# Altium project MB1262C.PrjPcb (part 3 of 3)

## Sheet USB_Host_Hub&OTG.SchDoc: USB_Host_Hub
size A3; DocumentNumber: MB1262; Revision: C-01; SheetNumber: 8; SheetTotal: 17; Project: STM32MP15x-EVAL
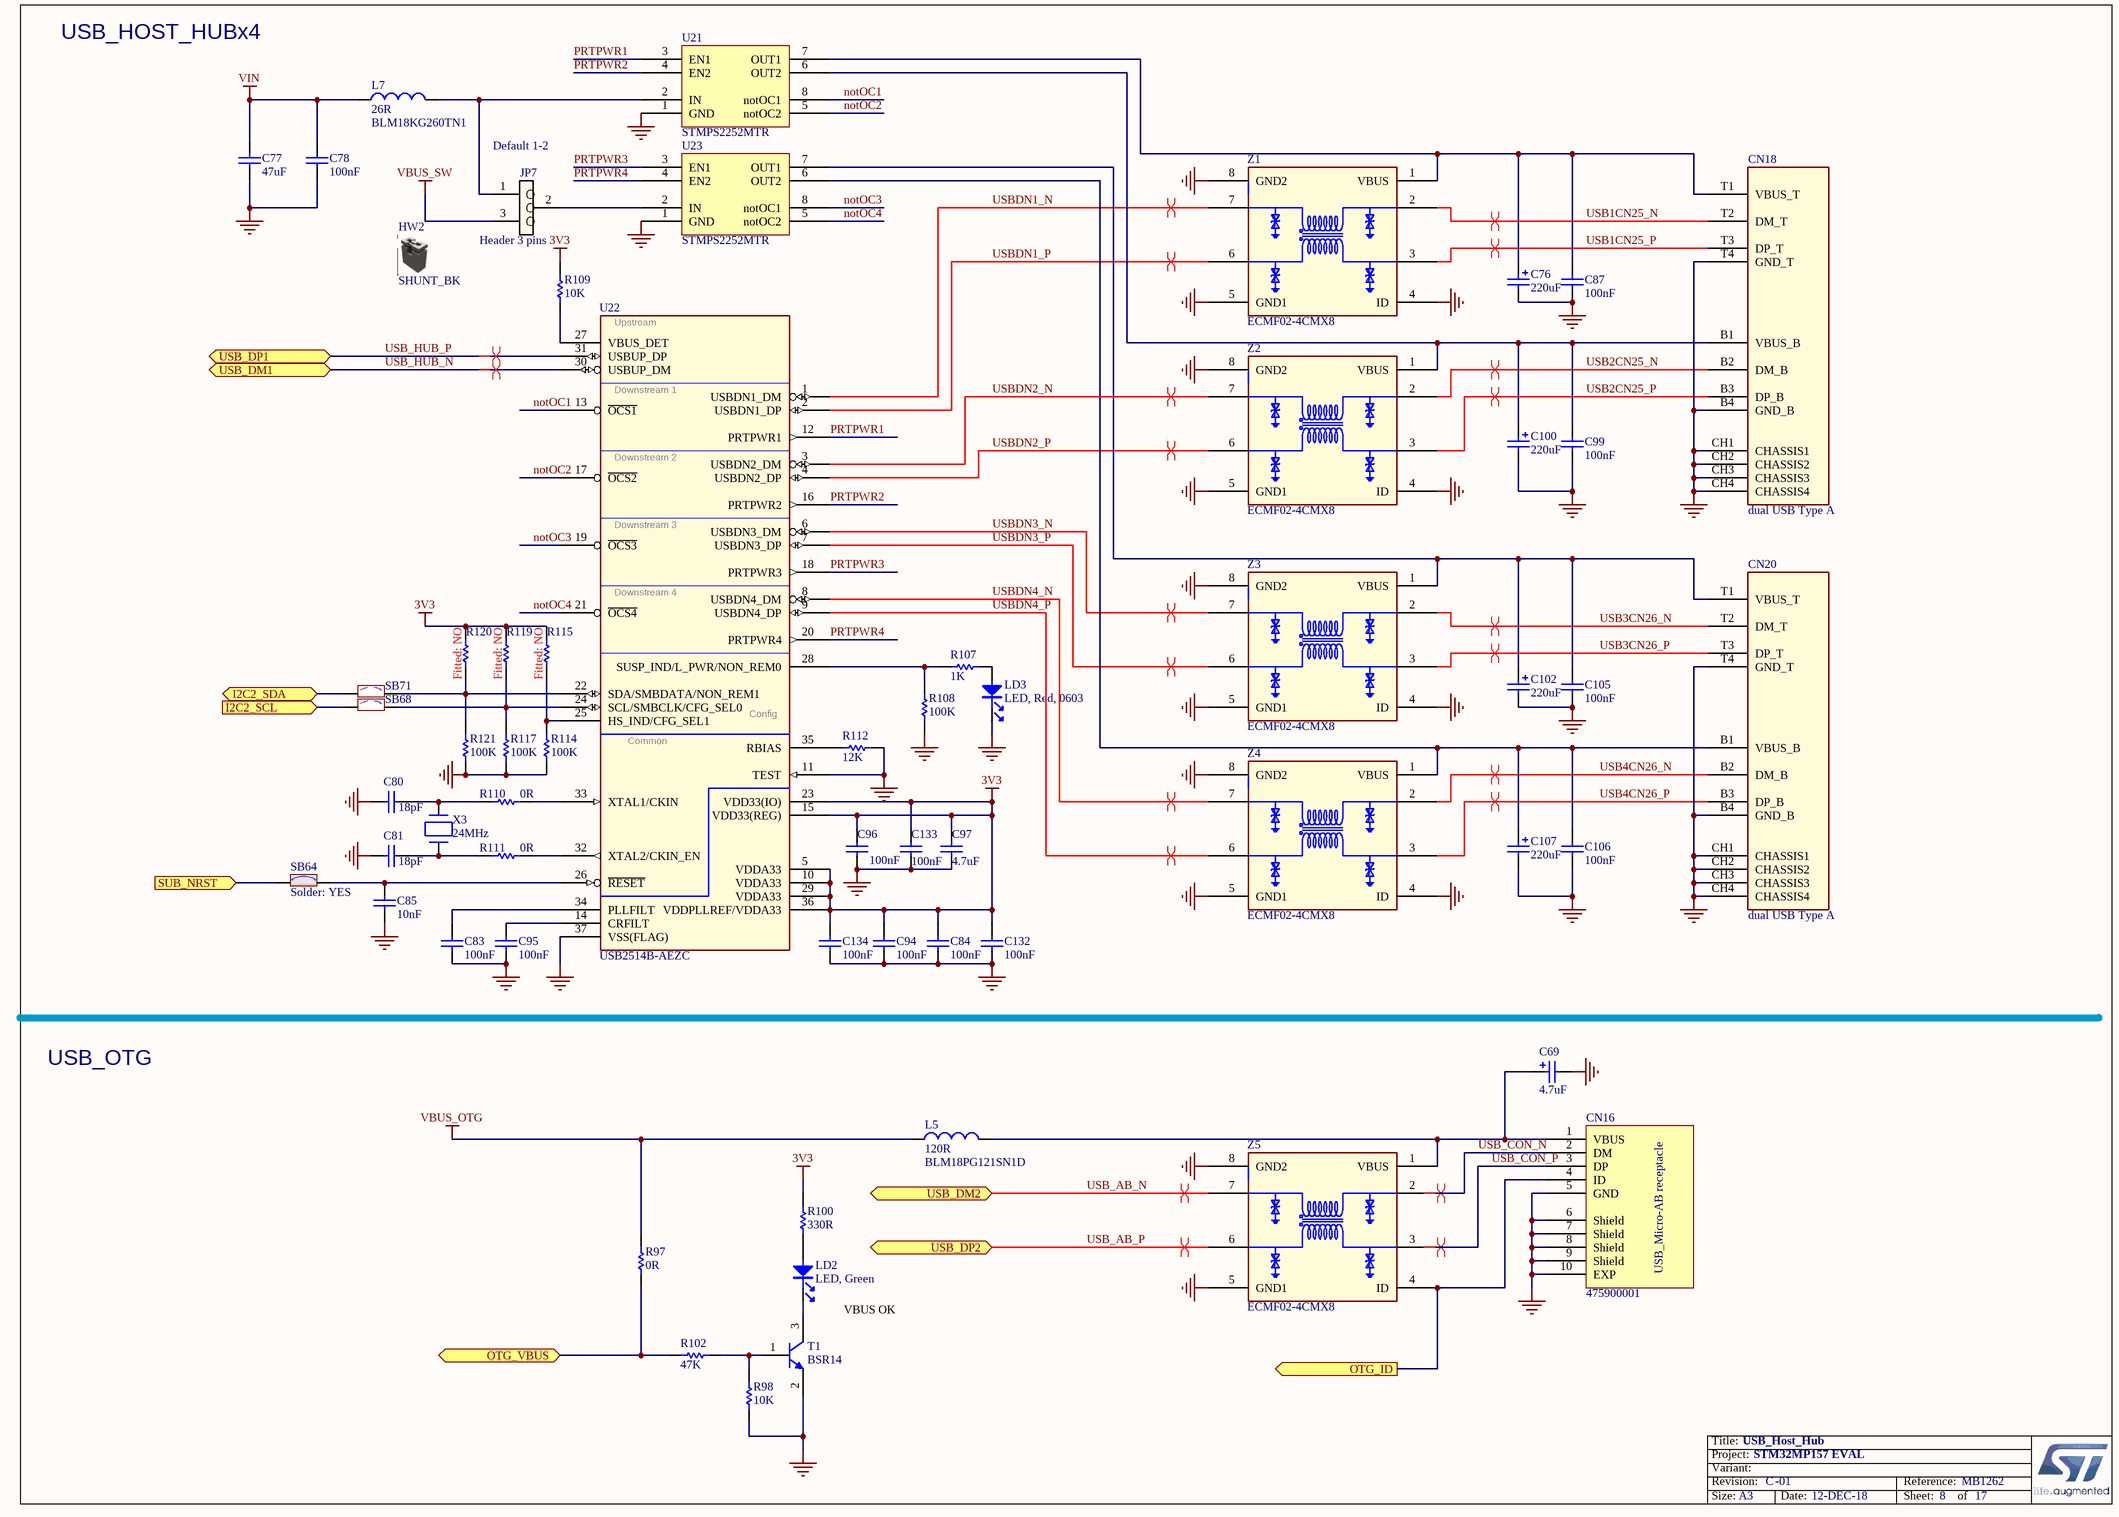
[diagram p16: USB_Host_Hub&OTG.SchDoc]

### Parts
C69  4.7uF  [CPOL_TAJ-A_1206_H180]
C76  220uF  [CPOL_TAJ-C_2312_H2P6]
C77  47uF  [C0805]
C78  100nF  [C0402]
C80  18pF  [C0402]
C81  18pF  [C0402]
C83  100nF  [C0402]
C84  100nF  [C0402]
C85  10nF  [C0402]
C87  100nF  [C0402]
C94  100nF  [C0402]
C95  100nF  [C0402]
C96  100nF  [C0402]
C97  4.7uF  [C0402]
C99  100nF  [C0402]
C100  220uF  [CPOL_TAJ-C_2312_H2P6]
C102  220uF  [CPOL_TAJ-C_2312_H2P6]
C105  100nF  [C0402]
C106  100nF  [C0402]
C107  220uF  [CPOL_TAJ-C_2312_H2P6]
C132  100nF  [C0402]
C133  100nF  [C0402]
C134  100nF  [C0402]
CN16  475900001  [CON_USBMICROAB_MOLEX_47590-0001_H3]
CN18  dual USB Type A  [CON_DUAL-USB-TYPE-A_CONEXCON_5600-3081]
CN20  dual USB Type A  [CON_DUAL-USB-TYPE-A_CONEXCON_5600-3081]
HW2  SHUNT_BK  (mechanical)
JP7  Header 3 pins  [CON_SAMTEC_TSW-103-07-F-S]
L5  120R  Manuf_Part_1: BLM18PG121SN1D  [FIL_0603_H065]
L7  26R  Manuf_Part_1: BLM18KG260TN1  [FIL_0603_H065]
LD2  LED, Green  [LED_0603_GREEN]
LD3  LED, Red, 0603  [LED_0603_RED]
R97  0R  [R0402]
R98  10K  [R0402]
R100  330R  [R0402]
R102  47K  [R0402]
R107  1K  [R0402]
R108  100K  [R0402]
R109  10K  [R0402]
R110  0R  [R0402]
R111  0R  [R0402]
R112  12K  [R0402]
R114  100K  [R0402]
R115  Fitted: NO  [R0402]  (hidden comment: 100K)
R117  100K  [R0402]
R119  Fitted: NO  [R0402]  (hidden comment: 100K)
R120  Fitted: NO  [R0402]  (hidden comment: 100K)
R121  100K  [R0402]
SB64  Solder: YES  [SOLDER-BRIDGE_R0603-0R]  (hidden comment: SB_ON)
SB68  SB_OFF  [SOLDER-BRIDGE_R0603-0R]  (value not drawn)
SB71  SB_OFF  [SOLDER-BRIDGE_R0603-0R]  (value not drawn)
T1  BSR14  [NPN_SOT23]
U21  STMPS2252MTR  [ICC_SO8_5X4_P127]
U22  USB2514B-AEZC  [ICC_QFN36-EPAD_6X6_P050]
U23  STMPS2252MTR  [ICC_SO8_5X4_P127]
X3  24MHz  [CRY_TXC_7A-SERIES_5X3P2_H1P2_2P]
Z1  ECMF02-4CMX8  [ESD_UQFN-8L_2P5X1P2_P050]
Z2  ECMF02-4CMX8  [ESD_UQFN-8L_2P5X1P2_P050]
Z3  ECMF02-4CMX8  [ESD_UQFN-8L_2P5X1P2_P050]
Z4  ECMF02-4CMX8  [ESD_UQFN-8L_2P5X1P2_P050]
Z5  ECMF02-4CMX8  [ESD_UQFN-8L_2P5X1P2_P050]

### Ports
I2C2_SCL (in), I2C2_SDA (bidir), OTG_ID (out), OTG_VBUS (bidir), SUB_NRST (in), USB_DM1 (bidir), USB_DM2 (bidir), USB_DP1 (bidir), USB_DP2 (bidir)

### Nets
3V3: C84.2 C94.2 C96.2 C97.2 C132.2 C133.2 C134.2 R100.2 R109.2 R115.2 R119.2 R120.2 U22.5(VDDA33) U22.10(VDDA33) U22.15(VDD33(REG)) U22.23(VDD33(IO)) U22.29(VDDA33) U22.36(VDDPLLREF/VDDA33)
GND: C69.2 C76.2 C77.1 C78.1 C80.1 C81.1 C83.1 C84.1 C85.1 C87.1 C94.1 C95.1 C96.1 C97.1 C99.1 C100.2 C102.2 C105.1 C106.1 C107.2 C132.1 C133.1 C134.1 CN16.5(GND) CN16.6(Shield) CN16.7(Shield) CN16.8(Shield) CN16.9(Shield) CN16.10(EXP) CN18.B4(GND_B) CN18.CH1(CHASSIS1) CN18.CH2(CHASSIS2) CN18.CH3(CHASSIS3) CN18.CH4(CHASSIS4) CN18.T4(GND_T) CN20.B4(GND_B) CN20.CH1(CHASSIS1) CN20.CH2(CHASSIS2) CN20.CH3(CHASSIS3) CN20.CH4(CHASSIS4) CN20.T4(GND_T) LD3.2 R98.1 R108.1 R112.2 R114.1 R117.1 R121.1 T1.2(E) U21.1(GND) U22.11(TEST) U22.37(VSS(FLAG)) U23.1(GND) Z1.4(ID) Z1.5(GND1) Z1.8(GND2) Z2.4(ID) Z2.5(GND1) Z2.8(GND2) Z3.4(ID) Z3.5(GND1) Z3.8(GND2) Z4.4(ID) Z4.5(GND1) Z4.8(GND2) Z5.5(GND1) Z5.8(GND2)
VBUS_OTG: L5.1 R97.2
VBUS_SW: JP7.3
VIN: C77.2 C78.2 L7.1
I2C2_SCL: SB68.1 ; port I2C2_SCL
I2C2_SDA: SB71.1 ; port I2C2_SDA
notOC1: U21.8(notOC1) U22.13(~{OCS1})
notOC2: U21.5(notOC2) U22.17(~{OCS2})
notOC3: U22.19(~{OCS3}) U23.8(notOC1)
notOC4: U22.21(~{OCS4}) U23.5(notOC2)
OTG_ID: CN16.4(ID) Z5.4(ID) ; port OTG_ID
OTG_VBUS: R97.1 R102.1 ; port OTG_VBUS
PRTPWR1: U21.3(EN1) U22.12(PRTPWR1)
PRTPWR2: U21.4(EN2) U22.16(PRTPWR2)
PRTPWR3: U22.18(PRTPWR3) U23.3(EN1)
PRTPWR4: U22.20(PRTPWR4) U23.4(EN2)
USB1CN25_N: CN18.T2(DM_T) Z1.2(D-1)
USB1CN25_P: CN18.T3(DP_T) Z1.3(D+1)
USB2CN25_N: CN18.B2(DM_B) Z2.2(D-1)
USB2CN25_P: CN18.B3(DP_B) Z2.3(D+1)
USB3CN26_N: CN20.T2(DM_T) Z3.2(D-1)
USB3CN26_P: CN20.T3(DP_T) Z3.3(D+1)
USB4CN26_N: CN20.B2(DM_B) Z4.2(D-1)
USB4CN26_P: CN20.B3(DP_B) Z4.3(D+1)
USB_AB_N: Z5.7(D-2) ; port USB_DM2
USB_AB_P: Z5.6(D+2) ; port USB_DP2
USB_CON_N: CN16.2(DM) Z5.2(D-1)
USB_CON_P: CN16.3(DP) Z5.3(D+1)
USB_HUB_N: U22.30(USBUP_DM) ; port USB_DM1
USB_HUB_P: U22.31(USBUP_DP) ; port USB_DP1
USBDN1_N: U22.1(USBDN1_DM) Z1.7(D-2)
USBDN1_P: U22.2(USBDN1_DP) Z1.6(D+2)
USBDN2_N: U22.3(USBDN2_DM) Z2.7(D-2)
USBDN2_P: U22.4(USBDN2_DP) Z2.6(D+2)
USBDN3_N: U22.6(USBDN3_DM) Z3.7(D-2)
USBDN3_P: U22.7(USBDN3_DP) Z3.6(D+2)
USBDN4_N: U22.8(USBDN4_DM) Z4.7(D-2)
USBDN4_P: U22.9(USBDN4_DP) Z4.6(D+2)
NetC69_1: C69.1 CN16.1(VBUS) L5.2 Z5.1(VBUS)
NetC76_1: C76.1 C87.2 CN18.T1(VBUS_T) U21.7(OUT1) Z1.1(VBUS)
NetC80_2: C80.2 R110.1 X3.2(X2)
NetC81_2: C81.2 R111.1 X3.1(X1)
NetC83_2: C83.2 U22.34(PLLFILT)
NetC85_2: C85.2 SB64.2 U22.26(~{RESET})
NetC95_2: C95.2 U22.14(CRFILT)
NetC99_2: C99.2 C100.1 CN18.B1(VBUS_B) U21.6(OUT2) Z2.1(VBUS)
NetC102_1: C102.1 C105.2 CN20.T1(VBUS_T) U23.7(OUT1) Z3.1(VBUS)
NetC106_2: C106.2 C107.1 CN20.B1(VBUS_B) U23.6(OUT2) Z4.1(VBUS)
NetCN10_26: SB64.1 ; port SUB_NRST
NetJP7_1: JP7.1 L7.2 U21.2(IN)
NetJP7_2: JP7.2 U23.2(IN)
NetLD2_1: LD2.1 R100.1
NetLD2_2: LD2.2 T1.3(C)
NetLD3_1: LD3.1 R107.2
NetR98_2: R98.2 R102.2 T1.1(B)
NetR107_1: R107.1 R108.2 U22.28(SUSP_IND/L_PWR/NON_REM0)
NetR109_1: R109.1 U22.27(VBUS_DET)
NetR110_2: R110.2 U22.33(XTAL1/CKIN)
NetR111_2: R111.2 U22.32(XTAL2/CKIN_EN)
NetR112_1: R112.1 U22.35(RBIAS)
NetR114_2: R114.2 R115.1 U22.25(HS_IND/CFG_SEL1)
NetR117_2: R117.2 R119.1 SB68.2 U22.24(SCL/SMBCLK/CFG_SEL0)
NetR120_1: R120.1 R121.2 SB71.2 U22.22(SDA/SMBDATA/NON_REM1)

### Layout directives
differential pair: (no net found under the mark), USB1CN25_N, USB1CN25_P, USB2CN25_N, USB2CN25_P, USB3CN26_N, USB3CN26_P, USB4CN26_N, USB4CN26_P, USB_AB_N, USB_AB_P, USB_HUB_N, USB_HUB_P, USBDN1_N, USBDN1_P, USBDN2_N, USBDN2_P, USBDN3_N, USBDN3_P, USBDN4_N, USBDN4_P

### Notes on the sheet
- USB_HOST_HUBx4
- (near JP7) Default 1-2
- USB_OTG
- VBUS OK

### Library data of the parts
C69 = Cap_4.7uF_POL_10%_TANA: Polarized Capacitor,4.7uF,16V,10%,typeA,AVX; Manuf_Part_1: TAJA475K016R; Fitted: YES; Ordered_By: Subcon
C76 C100 C102 C107 = Cap_220uF_POL_10%_TAJA: Polarized Capacitor,220uF,10V,10%,AVX; Manuf_Part_1: TAJC227K010R; Fitted: YES; Ordered_By: Subcon
C77 = Cap_47uF_X5R_20%_0805: Capacitor,47uF,10V,X5R,20%,0805,MURATA; Manuf_Part_1: GRM21BR61A476ME15K; Fitted: YES; Ordered_By: Subcon
C78 C83 C84 C87 C94-C96 C99 C105 C106 C132-C134 = Cap_100nF_X7R_10%_0402: Capacitor,100nF,16V,X7R,10%,0402,YAGEO; Manuf_Part_1: CC0402KRX7R7BB104; Fitted: YES; Ordered_By: Subcon
C80 C81 = Cap_18pF_NPO_5%_0402: Capacitor,18pF,50V,NPO,5%,0402,YAGEO; Order_Code: CC0402JRNPO9BN180; Fitted: YES; Ordered_By: Subcon
C85 = Cap_10nF_X7R_10%_0402: Capacitor,10nF,16V,X7R,10%,0402,YAGEO; Manuf_Part_1: CC0402KRX7R7BB103; Fitted: YES; Ordered_By: Subcon
C97 = Cap_4.7uF_X5R_20%_6V3_0402: Capacitor MLCC 4,7µF 20% 6,3V 1,9uF@3,3V X5R 0402; Manuf_Part_1: GRM155R60J475ME87; Manuf_1: MURATA; Fitted: YES; Ordered_By: Subcon
CN16 = 475900001: USB-MICRO-AB, 47590-0001, SMT, MOLEX; Fitted: YES; Ordered_By: Subcon
CN18 CN20 = CONN_USB_DUAL_TYPEA: USB Dual Type A Receptacle 5600 Series.; Manuf_Part_1: 5600 - 3081; Manuf_1: CONEXCON; Manuf_2: Cliff; Manuf_Part_2: FCK002A; Fitted: YES; Ordered_By: Subcon
HW2 = Shunt 2.54mm: SHUNT 2.54mm BLACK; Manuf_1: SAMTEC; Manuf_Part_1: SNT-100-BK-G; Fitted: YES; Ordered_By: Subcon
JP7 = Header 3: Header, 3-Pin; Manuf_1: Samtec; Manuf_Part_1: TSW-103-07-F-S; Fitted: YES; Ordered_By: Subcon
L5 = BEAD_120R_2A_0603: Bead,120R at 100Mhz,2A,0603; Manuf_1: MURATA; Ordered_By: Subcon; Fitted: YES
L7 = BEAD_26R_6A_0603_1: Bead,26R at 100Mhz,6A,0603; Manuf_1: MURATA; Ordered_By: Subcon; Fitted: YES
LD2 = LED_green: Manuf_1: everlight; Manuf_Part_1: 19-213SYGC/S530-E2/TR8; ECCN_US/EU: EAR99/NEC; Fitted: YES; Ordered_By: Subcon
LD3 = LED_red: Manuf_1: everlight; Manuf_Part_1: 19-213-R6C-AP1Q2B/3T; ECCN_US/EU: EAR99/NEC; Fitted: YES; Ordered_By: Subcon
R97 R110 R111 = Res_0_5%_0402: Resistor,0R,0402,5%,YAGEO; Manuf_Part_1: RC0402JR-070RL; Order_Code: 2363467; Fitted: YES; Ordered_By: Subcon
R98 R109 = Res_10K_1%_0402: Resistor,10K,0402,1%,YAGEO; Manuf_Part_1: RC0402FR-0710KL; Order_Code: 9239359RL; Fitted: YES; Ordered_By: Subcon
R100 = Res_330_1%_0402: Resistor,330R,0402,1%,YAGEO; Manuf_Part_1: RC0402FR-07330RL; Fitted: YES; Ordered_By: Subcon
R102 = Res_47K_1%_0402: Resistor,47K,0402,1%,YAGEO; Manuf_Part_1: RC0402FR-0747KL; Order_Code: 9239430; Fitted: YES; Ordered_By: Subcon
R107 = Res_1K_1%_0402: Resistor,1K,0402,1%,YAGEO; Manuf_Part_1: RC0402FR-071KL; Fitted: YES; Ordered_By: Subcon
R108 R114 R117 R121 = Res_100K_1%_0402: Resistor,100K,0402,1%,YAGEO; Manuf_Part_2: RT0402FRE07100KL; Manuf_Part_1: RC0402FR-07100KL; Fitted: YES; Ordered_By: Subcon
R112 = Res_12K_1%_0402: Resistor,12K,0402,1%,YAGEO; Manuf_Part_1: 9C06031A1202FKHFT; Fitted: YES; Ordered_By: Subcon
R115 R119 R120 = Res_100K_1%_0402: Resistor,100K,0402,1%,YAGEO; Manuf_Part_2: RT0402FRE07100KL; Manuf_Part_1: RC0402FR-07100KL; Ordered_By: Subcon
SB64 = SB_ON: Solder Bridge ON; Ordered_by: Subcon
SB68 SB71 = SB_OFF: Solder Bridge OFF; Fitted: NO; Ordered_By: Subcon; Solder: NO
T1 = 9013-SOT23: NPN Bipolar Transistor; Manuf_1: NXP; Order_Code: 1081310; ECCN_US/EU: EAR99/NEC; Fitted: YES; Ordered_By: Subcon
U21 U23 = STMPS2252MTR: Enhanced dual channel power switches 500mA; Manuf_1: ST; Fitted: YES; Ordered_By: Subcon
U22 = USB2514B-AEZC: IC, USB2514B, 4 Port USB 2.0 Hub w/ Battery Chg, QFN36; Manuf_1: SMSC; Fitted: YES; Ordered_By: Subcon
X3 = XTAL_24M_7A-24.000MAAE-T: Crystal, 24.000MHz, 30ppm, 18pF, 7A-24.000MAAE-T; Manuf_1: TXC; Order_Code: 717-7A-24.000MAAE-T; Fitted: Yes; Ordered_By: Subcon
Z1-Z5 = FIL_EMIF_USB_2: Common mode filter with ESD protection for USB2.0 interface; Manuf_1: ST; Fitted: YES; Ordered_By: Subcon

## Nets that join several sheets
1V8: Audio (6 pins), DSI&TFT-LCD&Camera (10 pins), Samtec Connectors QSH_North_South (CN10.2 CN10.4)
2V8: DSI&TFT-LCD&Camera (8 pins), Samtec Connectors QSH_North_South (CN9.2 CN9.4 CN9.6 CN9.8)
3V3: NAND (10 pins), Audio (17 pins), Ethernet (L1.2 L2.2), Ethernet_connector (12 pins), DSI&TFT-LCD&Camera (5 pins), Peripherals (5 pins), RS232 (C65.1 U12.22 U12.26), MotorControl (CN22.28 R137.2), CAN_FD&TT (C73.2 R94.1 U18.5), QSPI (8 pins), MFX (13 pins), Samtec Connectors QSH_North_South (CN9.1 CN9.3 CN9.5 CN9.7), SmartCard (10 pins), USB_Host_Hub&OTG (18 pins)
GND: NAND (8 pins), Audio (59 pins), Ethernet (30 pins), Ethernet_connector (12 pins), DSI&TFT-LCD&Camera (44 pins), Peripherals (25 pins), RS232 (8 pins), MotorControl (27 pins), CAN_FD&TT (10 pins), JTAG&Trace (27 pins), QSPI (6 pins), MFX (16 pins), Samtec Connectors QSH_North_South (40 pins), SmartCard (15 pins), USB_Host_Hub&OTG (67 pins)
VBUS_OTG: Samtec Connectors QSH_North_South (CN9.11 CN9.13 CN9.15), USB_Host_Hub&OTG (L5.1 R97.2)
VBUS_SW: Samtec Connectors QSH_North_South (CN9.19 CN9.21 CN9.23), USB_Host_Hub&OTG (JP7.3)
VDD: JTAG&Trace (6 pins), Samtec Connectors QSH_North_South (CN10.8 CN10.10)
VIN: DSI&TFT-LCD&Camera (L4.2 L9.1), Peripherals (CN21.2 CN21.4 SB58.2), MotorControl (CN22.25), CAN_FD&TT (C70.2 U18.3), Samtec Connectors QSH_North_South (CN10.7 CN10.9 CN10.11), SmartCard (C3.2 C8.2 U5.6), USB_Host_Hub&OTG (C77.2 C78.2 L7.1)
Anti_TAMP2: MFX (R127.1), Samtec Connectors QSH_North_South (CN9.29)
CAN1_RX: CAN_FD&TT (U18.4), Samtec Connectors QSH_North_South (CN10.97)
CAN1_TX: CAN_FD&TT (U18.1), Samtec Connectors QSH_North_South (CN10.95 SB76.2)
CAN_STBY: CAN_FD&TT (R95.1 U18.8), Samtec Connectors QSH_North_South (CN9.39)
CLK125: Ethernet (R44.1), Ethernet_connector (CN6.22), Samtec Connectors QSH_North_South (CN9.51)
DCMI_D0: DSI&TFT-LCD&Camera (CN7.23), Samtec Connectors QSH_North_South (CN10.68)
DCMI_D1: DSI&TFT-LCD&Camera (CN7.24), Samtec Connectors QSH_North_South (CN10.71 SB28.2)
DCMI_D2: DSI&TFT-LCD&Camera (CN7.25), Samtec Connectors QSH_North_South (CN10.73 SB30.2)
DCMI_D3: DSI&TFT-LCD&Camera (CN7.26), Samtec Connectors QSH_North_South (CN10.64 SB26.2)
DCMI_D4: DSI&TFT-LCD&Camera (CN7.27), Samtec Connectors QSH_North_South (CN10.61 SB21.2)
DCMI_D5: DSI&TFT-LCD&Camera (CN7.28), Samtec Connectors QSH_North_South (CN10.66)
DCMI_D6: DSI&TFT-LCD&Camera (CN7.29), Samtec Connectors QSH_North_South (CN10.69 SB24.2)
DCMI_D7: DSI&TFT-LCD&Camera (CN7.30), Samtec Connectors QSH_North_South (CN10.72)
DCMI_D8: DSI&TFT-LCD&Camera (CN7.9), Samtec Connectors QSH_North_South (CN10.62)
DCMI_D9: DSI&TFT-LCD&Camera (CN7.10), Samtec Connectors QSH_North_South (CN10.65)
DCMI_D10: DSI&TFT-LCD&Camera (CN7.5), Samtec Connectors QSH_North_South (CN10.63)
DCMI_D11: DSI&TFT-LCD&Camera (CN7.6), Samtec Connectors QSH_North_South (CN10.75 SB33.2)
DCMI_HSYNC: DSI&TFT-LCD&Camera (CN7.31), Samtec Connectors QSH_North_South (CN10.70)
DCMI_PIXCK: DSI&TFT-LCD&Camera (CN7.33), Samtec Connectors QSH_North_South (CN10.67 SB22.2)
DCMI_VSYNC: DSI&TFT-LCD&Camera (CN7.32), Samtec Connectors QSH_North_South (CN10.74 SB32.2)
DFSDM_CKOUT: Audio (CN8.4 JP3.1 SB2.1), Samtec Connectors QSH_North_South (CN9.63)
DFSDM_DATA1: Audio (CN8.6 JP2.3), Samtec Connectors QSH_North_South (CN9.26)
DFSDM_DATA3: Audio (CN8.5 JP1.3), Samtec Connectors QSH_North_South (CN9.65)
DFSDM_DATA5: Audio (CN8.7), Samtec Connectors QSH_North_South (SB1.2)
DSI_CK_N: DSI&TFT-LCD&Camera (CN19.5), Samtec Connectors QSH_North_South (CN10.107)
DSI_CK_P: DSI&TFT-LCD&Camera (CN19.3), Samtec Connectors QSH_North_South (CN10.109)
DSI_D0_N: DSI&TFT-LCD&Camera (CN19.11), Samtec Connectors QSH_North_South (CN10.103)
DSI_D0_P: DSI&TFT-LCD&Camera (CN19.9), Samtec Connectors QSH_North_South (CN10.105)
DSI_D1_N: DSI&TFT-LCD&Camera (CN19.17), Samtec Connectors QSH_North_South (CN10.113)
DSI_D1_P: DSI&TFT-LCD&Camera (CN19.15), Samtec Connectors QSH_North_South (CN10.111)
DSI_RESET: DSI&TFT-LCD&Camera (CN19.57 R130.2), Samtec Connectors QSH_North_South (CN9.59)
DSI_TE: DSI&TFT-LCD&Camera (CN19.49), Samtec Connectors QSH_North_South (CN10.117)
ETH_GTX_CLK: Ethernet (U9.34), Ethernet_connector (CN6.24), Samtec Connectors QSH_North_South (CN9.46)
ETH_MDC: Ethernet (R69.1), Samtec Connectors QSH_North_South (CN9.38)
ETH_MDINT: Ethernet (R60.1 U9.56), Ethernet_connector (CN6.52), Samtec Connectors QSH_North_South (CN9.47)
ETH_MDIO: Ethernet (R65.1), Samtec Connectors QSH_North_South (CN9.36)
ETH_RX_CLK: Ethernet (R56.1), Samtec Connectors QSH_North_South (CN9.42)
ETH_RX_DV: Ethernet (R38.1 R39.2 R45.1), Samtec Connectors QSH_North_South (CN9.60)
ETH_RXD0: Ethernet (R48.1), Ethernet_connector (CN6.4), Samtec Connectors QSH_North_South (CN9.58)
ETH_RXD1: Ethernet (R51.1), Ethernet_connector (CN6.6), Samtec Connectors QSH_North_South (CN9.56)
ETH_RXD2: Ethernet (R52.1), Ethernet_connector (CN6.10), Samtec Connectors QSH_North_South (CN9.54)
ETH_RXD3: Ethernet (R55.1), Ethernet_connector (CN6.12), Samtec Connectors QSH_North_South (CN9.52)
ETH_TX_EN: Ethernet (U9.35), Ethernet_connector (CN6.28), Samtec Connectors QSH_North_South (CN9.50)
ETH_TXD0: Ethernet (U9.36), Ethernet_connector (CN6.34), Samtec Connectors QSH_North_South (CN9.34)
ETH_TXD1: Ethernet (U9.39), Ethernet_connector (CN6.36), Samtec Connectors QSH_North_South (CN9.32)
ETH_TXD2: Ethernet (U9.40), Ethernet_connector (CN6.40), Samtec Connectors QSH_North_South (CN9.30)
ETH_TXD3: Ethernet (U9.41), Ethernet_connector (CN6.42), Samtec Connectors QSH_North_South (CN9.28)
EXP_GPIO2: Peripherals (CN21.3), Samtec Connectors QSH_North_South (SB55.1)
EXP_GPIO3: Peripherals (CN21.5), Samtec Connectors QSH_North_South (SB52.1)
EXP_GPIO4: Peripherals (CN21.7), Samtec Connectors QSH_North_South (CN9.33)
EXP_GPIO5: Peripherals (CN21.29), Samtec Connectors QSH_North_South (CN9.43)
EXP_GPIO6: Peripherals (CN21.31), Samtec Connectors QSH_North_South (SB15.1)
EXP_GPIO7: Peripherals (CN21.26), Samtec Connectors QSH_North_South (SB17.1)
EXP_GPIO8: Peripherals (CN21.24), Samtec Connectors QSH_North_South (CN10.85)
EXP_GPIO9: Peripherals (CN21.21), Samtec Connectors QSH_North_South (CN10.84)
EXP_GPIO10: Peripherals (CN21.19), Samtec Connectors QSH_North_South (CN10.82)
EXP_GPIO11: Peripherals (CN21.23), Samtec Connectors QSH_North_South (CN10.83)
EXP_GPIO12: Peripherals (CN21.32), Samtec Connectors QSH_North_South (SB27.1)
EXP_GPIO13: Peripherals (CN21.33), Samtec Connectors QSH_North_South (CN10.81)
EXP_GPIO14: Peripherals (CN21.8), Samtec Connectors QSH_North_South (CN9.61)
EXP_GPIO15: Peripherals (CN21.10), Samtec Connectors QSH_North_South (CN9.71)
EXP_GPIO16: Peripherals (CN21.36), Samtec Connectors QSH_North_South (CN9.31)
EXP_GPIO17: Peripherals (CN21.11), Samtec Connectors QSH_North_South (SB23.1)
EXP_GPIO18: Peripherals (CN21.12), Samtec Connectors QSH_North_South (SB66.1)
EXP_GPIO19: Peripherals (CN21.35), Samtec Connectors QSH_North_South (SB63.1)
EXP_GPIO20: Peripherals (CN21.38), Samtec Connectors QSH_North_South (SB73.1)
EXP_GPIO21: Peripherals (CN21.40), Samtec Connectors QSH_North_South (SB69.1)
EXP_GPIO22: Peripherals (CN21.15), Samtec Connectors QSH_North_South (CN10.89)
EXP_GPIO23: Peripherals (CN21.16), Samtec Connectors QSH_North_South (CN10.80)
EXP_GPIO24: Peripherals (CN21.18), Samtec Connectors QSH_North_South (CN10.91)
EXP_GPIO25: Peripherals (CN21.22), Samtec Connectors QSH_North_South (CN10.87)
EXP_GPIO26: Peripherals (CN21.37), Samtec Connectors QSH_North_South (CN10.86)
EXP_GPIO27: Peripherals (CN21.13), Samtec Connectors QSH_North_South (CN10.88)
HDMI_CEC: DSI&TFT-LCD&Camera (CN11.51), Samtec Connectors QSH_North_South (CN10.93)
HDMI_PD: DSI&TFT-LCD&Camera (CN11.13), MFX (U20.11)
I2C2_SCL: Audio (R49.2), DSI&TFT-LCD&Camera (CN11.53 CN19.44 R17.1 TR2.3), MFX (R124.1), Samtec Connectors QSH_North_South (CN10.79 SB74.2), USB_Host_Hub&OTG (SB68.1)
I2C2_SDA: Audio (R50.2), DSI&TFT-LCD&Camera (CN11.55 CN19.40 R12.1 TR1.3), MFX (R125.1), Samtec Connectors QSH_North_South (CN10.78 SB72.2), USB_Host_Hub&OTG (SB71.1)
ID_SC: Peripherals (CN21.28), Samtec Connectors QSH_North_South (SB74.1)
ID_SD: Peripherals (CN21.27), Samtec Connectors QSH_North_South (SB72.1)
JTCK_SWCLK: JTAG&Trace (CN14.9 U10.15 U16.3), Samtec Connectors QSH_North_South (CN10.100)
JTDI: JTAG&Trace (CN14.5 U10.19 U13.5), Samtec Connectors QSH_North_South (CN10.98)
JTDO_TRACESWO: JTAG&Trace (CN14.13 U10.11 U16.4), Samtec Connectors QSH_North_South (CN10.104)
JTMS_SWDIO: JTAG&Trace (CN14.7 U10.17 U16.1), Samtec Connectors QSH_North_South (CN10.106)
LCD_BL_CTRL: DSI&TFT-LCD&Camera (CN11.57 CN19.53), Samtec Connectors QSH_North_South (CN9.111)
LCD_INT: DSI&TFT-LCD&Camera (CN11.4 CN19.4), MFX (U20.27)
LTDC_B0: DSI&TFT-LCD&Camera (CN11.39), Samtec Connectors QSH_North_South (CN10.57)
LTDC_B1: DSI&TFT-LCD&Camera (CN11.40), Samtec Connectors QSH_North_South (CN10.54)
LTDC_B2: DSI&TFT-LCD&Camera (CN11.41), Samtec Connectors QSH_North_South (CN10.56)
LTDC_B3: DSI&TFT-LCD&Camera (CN11.42), Samtec Connectors QSH_North_South (CN10.55)
LTDC_B4: DSI&TFT-LCD&Camera (CN11.27), Samtec Connectors QSH_North_South (CN10.51)
LTDC_B5: DSI&TFT-LCD&Camera (CN11.28), Samtec Connectors QSH_North_South (CN10.52)
LTDC_B6: DSI&TFT-LCD&Camera (CN11.31), Samtec Connectors QSH_North_South (CN10.53 SB49.1)
LTDC_B7: DSI&TFT-LCD&Camera (CN11.6), Samtec Connectors QSH_North_South (CN10.50 SB35.1)
LTDC_CLK: DSI&TFT-LCD&Camera (CN11.58), Samtec Connectors QSH_North_South (CN10.36 SB38.1)
LTDC_DE: DSI&TFT-LCD&Camera (R82.2), Samtec Connectors QSH_North_South (CN10.49)
LTDC_G0: DSI&TFT-LCD&Camera (CN11.30), Samtec Connectors QSH_North_South (CN10.43 SB45.1)
LTDC_G1: DSI&TFT-LCD&Camera (CN11.33), Samtec Connectors QSH_North_South (CN10.41 SB44.1)
LTDC_G2: DSI&TFT-LCD&Camera (CN11.34), Samtec Connectors QSH_North_South (CN10.37 SB50.1)
LTDC_G3: DSI&TFT-LCD&Camera (CN11.37), Samtec Connectors QSH_North_South (CN10.42)
LTDC_G4: DSI&TFT-LCD&Camera (CN11.38), Samtec Connectors QSH_North_South (CN10.48)
LTDC_G5: DSI&TFT-LCD&Camera (CN11.23), Samtec Connectors QSH_North_South (CN10.60)
LTDC_G6: DSI&TFT-LCD&Camera (CN11.24), Samtec Connectors QSH_North_South (CN10.58 SB40.1)
LTDC_G7: DSI&TFT-LCD&Camera (CN11.49), Samtec Connectors QSH_North_South (CN10.59 SB39.1)
LTDC_HSYNC: DSI&TFT-LCD&Camera (CN11.9), Samtec Connectors QSH_North_South (CN10.33 SB43.1)
LTDC_R0: DSI&TFT-LCD&Camera (CN11.14), Samtec Connectors QSH_North_South (CN10.47)
LTDC_R1: DSI&TFT-LCD&Camera (CN11.17), Samtec Connectors QSH_North_South (CN10.39 SB34.1)
LTDC_R2: DSI&TFT-LCD&Camera (CN11.18), Samtec Connectors QSH_North_South (CN10.46 SB37.1)
LTDC_R3: DSI&TFT-LCD&Camera (CN11.21), Samtec Connectors QSH_North_South (CN10.44 SB48.1)
LTDC_R4: DSI&TFT-LCD&Camera (CN11.22), Samtec Connectors QSH_North_South (CN10.35 SB47.1)
LTDC_R5: DSI&TFT-LCD&Camera (CN11.7 CN11.25), Samtec Connectors QSH_North_South (CN10.40 SB46.1)
LTDC_R6: DSI&TFT-LCD&Camera (CN11.26), Samtec Connectors QSH_North_South (CN10.38 SB36.1)
LTDC_R7: DSI&TFT-LCD&Camera (CN11.2 CN11.29), Samtec Connectors QSH_North_South (CN10.45 SB41.1)
LTDC_VSYNC: DSI&TFT-LCD&Camera (CN11.10), Samtec Connectors QSH_North_South (CN10.34 SB42.1)
MC_BusVoltage: MotorControl (C117.2 R135.2 R136.2), Samtec Connectors QSH_North_South (SB14.1)
MC_CurrentA: MotorControl (C116.2 R134.1), Samtec Connectors QSH_North_South (SB20.1)
MC_CurrentB: MotorControl (C115.2 R133.1), Samtec Connectors QSH_North_South (SB12.1)
MC_CurrentC: MotorControl (C114.2 R132.1), Samtec Connectors QSH_North_South (SB13.1)
MC_DissipativeBrake: MotorControl (CN22.23), Samtec Connectors QSH_North_South (SB29.1)
MC_EmergencySTOP: MotorControl (R83.1), Samtec Connectors QSH_North_South (SB22.1)
MC_EnA: MotorControl (C110.2 CN22.31 SB25.2), Samtec Connectors QSH_North_South (SB28.1)
MC_EnB: MotorControl (C109.2 CN22.33), Samtec Connectors QSH_North_South (SB30.1)
MC_EnIndex: MotorControl (C108.1 CN22.34), Samtec Connectors QSH_North_South (SB26.1)
MC_Heatsink: MotorControl (C113.2 R131.2), Samtec Connectors QSH_North_South (SB70.1)
MC_NTC: MotorControl (CN22.21), Samtec Connectors QSH_North_South (SB19.1)
MC_PFCpwm: MotorControl (C111.2 CN22.29), Samtec Connectors QSH_North_South (SB24.1)
MC_PFCsync1: MotorControl (C60.2 SB31.1), Samtec Connectors QSH_North_South (SB32.1)
MC_PFCsync2: MotorControl (C112.2 CN22.27 SB31.2), Samtec Connectors QSH_North_South (SB53.1)
MC_UH: MotorControl (CN22.3), Samtec Connectors QSH_North_South (SB67.1)
MC_UL: MotorControl (CN22.5), Samtec Connectors QSH_North_South (SB76.1)
MC_VH: MotorControl (CN22.7), Samtec Connectors QSH_North_South (SB75.1)
MC_VL: MotorControl (CN22.9), Samtec Connectors QSH_North_South (SB21.1)
MC_WH: MotorControl (CN22.11), Samtec Connectors QSH_North_South (SB65.1)
MC_WL: MotorControl (CN22.13), Samtec Connectors QSH_North_South (SB33.1)
MDC: Ethernet (R66.1 R69.2 U9.53), Ethernet_connector (CN6.46)
MDIO: Ethernet (R63.1 R65.2 U9.54), Ethernet_connector (CN6.48)
MIC_MEMS_LED: Audio (CN8.12), MFX (U20.31)
NAND_ALE: NAND (U11.C4), Samtec Connectors QSH_North_South (CN9.101)
NAND_CLE: NAND (U11.D5), Samtec Connectors QSH_North_South (CN9.89)
NAND_D0: NAND (U11.H4), Samtec Connectors QSH_North_South (CN9.87)
NAND_D1: NAND (U11.J4), Samtec Connectors QSH_North_South (CN9.81)
NAND_D2: NAND (U11.K4), Samtec Connectors QSH_North_South (CN10.29)
NAND_D3: NAND (U11.K5), Samtec Connectors QSH_North_South (CN10.27)
NAND_D4: NAND (U11.K6), Samtec Connectors QSH_North_South (CN9.91)
NAND_D5: NAND (U11.J7), Samtec Connectors QSH_North_South (CN9.95)
NAND_D6: NAND (U11.K7), Samtec Connectors QSH_North_South (CN9.93)
NAND_D7: NAND (U11.J8), Samtec Connectors QSH_North_South (CN9.99)
NAND_NCE: NAND (R84.1 U11.C6), Samtec Connectors QSH_North_South (CN9.97)
NAND_NOE: NAND (U11.D4), Samtec Connectors QSH_North_South (CN10.30)
NAND_NWAIT: NAND (U11.C8), Samtec Connectors QSH_North_South (CN10.24)
NAND_NWE: NAND (U11.C7), Samtec Connectors QSH_North_South (CN10.28)
NetC74_2: Peripherals (C74.2 R105.1), MFX (U20.18)
NetCN7_15: DSI&TFT-LCD&Camera (CN7.15 R19.1), MFX (U20.33)
NetCN7_17: DSI&TFT-LCD&Camera (CN7.17 R21.2), MFX (U20.13)
NetCN7_19: DSI&TFT-LCD&Camera (CN7.19 R28.2), MFX (U20.12)
NetCN10_26: Ethernet (R73.1), DSI&TFT-LCD&Camera (SB16.1), MFX (D1.2), Samtec Connectors QSH_North_South (CN10.26), USB_Host_Hub&OTG (SB64.1)
NetCN13_1: Peripherals (CN13.1), Samtec Connectors QSH_North_South (SB54.2)
NetCN13_3: Peripherals (CN13.3), Samtec Connectors QSH_North_South (SB51.2)
NetCN13_4: Peripherals (CN13.4), MFX (U20.10)
NetR5_2: MFX (U20.16), SmartCard (R5.2 U5.3)
NetR22_1: MFX (U20.30), SmartCard (R22.1 U5.19)
NetR23_1: MFX (U20.29), SmartCard (R23.1 U5.20)
NetR24_2: MFX (U20.17), SmartCard (R24.2 U5.23)
NetR54_1: Audio (R54.1), Samtec Connectors QSH_North_South (SB11.2)
NetR77_1: Ethernet_connector (R77.1), Samtec Connectors QSH_North_South (SB77.2)
NetR103_1: Peripherals (R103.1), MFX (U20.20)
NetR104_1: Peripherals (R104.1), MFX (U20.19)
NetR122_1: Peripherals (R122.1), MFX (U20.39)
NetR123_1: Peripherals (R123.1), MFX (U20.40)
NetSB4_1: Audio (SB4.1 SB5.1), Samtec Connectors QSH_North_South (SB8.2)
NetSB6_2: Audio (U8.H2), Samtec Connectors QSH_North_South (SB6.2)
NetSB7_2: Audio (U8.D3), Samtec Connectors QSH_North_South (SB7.2)
NetSB9_2: Audio (U8.G1), Samtec Connectors QSH_North_South (SB9.2)
NetSB10_2: Audio (U8.E4), Samtec Connectors QSH_North_South (SB10.2)
NetSB38_2: JTAG&Trace (U10.6), Samtec Connectors QSH_North_South (SB38.2)
NetU8_G3: Audio (U8.G3), MFX (U20.15)
NJTRST: JTAG&Trace (CN14.3 U10.21 U13.4), Samtec Connectors QSH_North_South (CN10.102)
NRST: Peripherals (SB62.1), JTAG&Trace (CN14.15 U10.9 U16.5), Samtec Connectors QSH_North_South (CN10.17)
OTG_ID: Samtec Connectors QSH_North_South (CN9.98), USB_Host_Hub&OTG (CN16.4 Z5.4)
OTG_VBUS: Samtec Connectors QSH_North_South (CN9.100), USB_Host_Hub&OTG (R97.1 R102.1)
PA0_WKUP: MFX (R118.1), Samtec Connectors QSH_North_South (CN10.15)
PA13: RS232 (SB56.1), Samtec Connectors QSH_North_South (CN9.25)
PA14: JTAG&Trace (SB18.2), Samtec Connectors QSH_North_South (CN9.27)
PHYRSTB: Ethernet (R73.2 U9.38), Ethernet_connector (CN6.54)
QSPI_BK1_IO0: QSPI (U14.D3), Samtec Connectors QSH_North_South (CN9.76)
QSPI_BK1_IO1: QSPI (U14.D2), Samtec Connectors QSH_North_South (CN9.78)
QSPI_BK1_IO2: QSPI (U14.C4), Samtec Connectors QSH_North_South (CN9.80)
QSPI_BK1_IO3: QSPI (U14.D4), Samtec Connectors QSH_North_South (CN9.82)
QSPI_BK1_NCS: QSPI (SB59.1), Samtec Connectors QSH_North_South (CN9.74)
QSPI_BK2_IO0: QSPI (U15.D3), Samtec Connectors QSH_North_South (CN9.64)
QSPI_BK2_IO1: QSPI (U15.D2), Samtec Connectors QSH_North_South (CN9.66)
QSPI_BK2_IO2: QSPI (U15.C4), Samtec Connectors QSH_North_South (CN9.68)
QSPI_BK2_IO3: QSPI (U15.D4), Samtec Connectors QSH_North_South (CN9.70)
QSPI_BK2_NCS: QSPI (SB60.1), Samtec Connectors QSH_North_South (CN9.72)
QSPI_CLK: QSPI (U14.B2 U15.B2), Samtec Connectors QSH_North_South (CN9.62)
RXCLK: Ethernet (R56.2 U9.24), Ethernet_connector (R74.1)
RXDV_PHY_AD2: Ethernet (R45.2 U9.18), Ethernet_connector (CN6.16)
SAI2_FSB: Audio (U8.F4), Samtec Connectors QSH_North_South (CN10.14)
SAI2_MCLKB: Audio (U8.E1), Samtec Connectors QSH_North_South (CN10.16)
SAI4_SD_A: Audio (R13.1 TP3.1), DSI&TFT-LCD&Camera (R75.1), Samtec Connectors QSH_North_South (CN9.75)
SmartCard_CLK: Samtec Connectors QSH_North_South (CN9.20), SmartCard (U5.24)
SmartCard_IO: Samtec Connectors QSH_North_South (CN9.22), SmartCard (R25.2)
SPDIF_RX: Audio (R16.2 R29.2 U7.4), Samtec Connectors QSH_North_South (CN10.120)
TRACED0: JTAG&Trace (U10.38), Samtec Connectors QSH_North_South (SB43.2)
TRACED1: JTAG&Trace (U10.28), Samtec Connectors QSH_North_South (SB42.2)
TRACED2: JTAG&Trace (U10.26), Samtec Connectors QSH_North_South (SB36.2)
TRACED3: JTAG&Trace (U10.24), Samtec Connectors QSH_North_South (SB41.2)
TRACED4: JTAG&Trace (U10.22), Samtec Connectors QSH_North_South (SB40.2)
TRACED5: JTAG&Trace (U10.20), Samtec Connectors QSH_North_South (SB39.2)
TRACED6: JTAG&Trace (U10.18), Samtec Connectors QSH_North_South (SB49.2)
TRACED7: JTAG&Trace (U10.16), Samtec Connectors QSH_North_South (SB35.2)
TRACED8: JTAG&Trace (U10.37), Samtec Connectors QSH_North_South (SB34.2)
TRACED9: JTAG&Trace (U10.35), Samtec Connectors QSH_North_South (SB37.2)
TRACED10: JTAG&Trace (U10.33), Samtec Connectors QSH_North_South (SB48.2)
TRACED11: JTAG&Trace (U10.31), Samtec Connectors QSH_North_South (SB47.2)
TRACED12: JTAG&Trace (U10.29), Samtec Connectors QSH_North_South (SB46.2)
TRACED13: JTAG&Trace (U10.27), Samtec Connectors QSH_North_South (SB45.2)
TRACED14: JTAG&Trace (U10.25), Samtec Connectors QSH_North_South (SB44.2)
TRACED15: JTAG&Trace (U10.23), Samtec Connectors QSH_North_South (SB50.2)
UART4_RX: RS232 (U12.17), Samtec Connectors QSH_North_South (CN9.115)
UART4_TX: RS232 (SB57.1), Samtec Connectors QSH_North_South (CN9.113)
USB_AB_N: Samtec Connectors QSH_North_South (CN9.86), USB_Host_Hub&OTG (Z5.7)
USB_AB_P: Samtec Connectors QSH_North_South (CN9.88), USB_Host_Hub&OTG (Z5.6)
USB_HUB_N: Samtec Connectors QSH_North_South (CN9.94), USB_Host_Hub&OTG (U22.30)
USB_HUB_P: Samtec Connectors QSH_North_South (CN9.92), USB_Host_Hub&OTG (U22.31)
